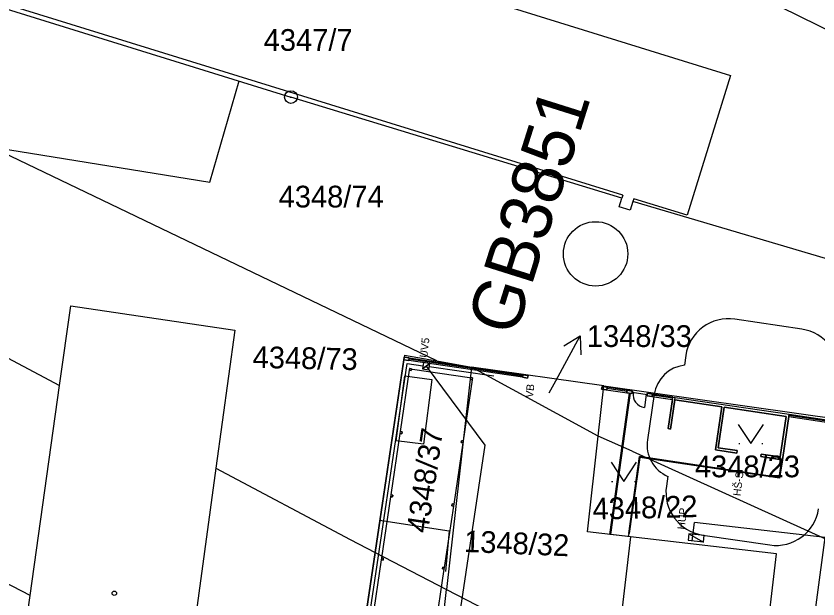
# Model space of a CAD drawing. Extents: x -735036 to -734743, y -1144813 to -1144181.
# Drawn here: x -734898.4 to -734835.7, y -1144525.7 to -1144480 of the extents above; entities that cross this region are included whole.
import ezdxf

# ---------------------------------------------------------------- set-up
doc = ezdxf.new("R2010")
doc.units = 0
for name, color, linetype in [('A3_BOURANÉ OBJEKTY', 7, 'Continuous'), ('A3_Netisk', 7, 'Continuous'), ('A3_ODVODŇOVACÍ ŽLAB', 7, 'Continuous'), ('A3_SIT_OBJEKTY_N01', 7, 'Continuous'), ('A3_SIT_PNB', 7, 'Continuous'), ('CKKOTY', 7, 'Continuous'), ('CKPLYN_POTRUBI_NT_PODZ_N', 7, 'Continuous'), ('CKTEXTY_MALE', 7, 'Continuous'), ('hranice pl. určené SŽDC', 7, 'Continuous'), ('Katastr_HRANICE DRÁHY', 7, 'Continuous'), ('Katastr_Hranice parcel', 7, 'Continuous'), ('Katastr_Parcelní čísla', 7, 'Continuous'), ('Katastr_Značky kultur', 7, 'Continuous'), ('SO05_CKKANALIZACE_JEDNOTNA_PODZ_N', 7, 'Continuous'), ('ŽBP', 7, 'Continuous')]:
    doc.layers.add(name, color=color, linetype=linetype)

msp = doc.modelspace()

# ---------------------------------------------------------------- linework, layer by layer
msp.add_line((-734866.625, -1144507.658), (-734866.057, -1144507.237))
for points in [[(-734866.625, -1144507.658), (-734866.13, -1144507.731), (-734866.057, -1144507.237), (-734866.551, -1144507.163)], [(-734866.625, -1144507.658), (-734866.13, -1144507.731), (-734866.057, -1144507.237)]]:
    msp.add_lwpolyline(points, close=True)
at = {"layer": 'A3_BOURANÉ OBJEKTY'}
msp.add_lwpolyline([(-734866.552, -1144513.548), (-734868.669, -1144513.299), (-734867.996, -1144508.198), (-734865.894, -1144508.483)], close=True, dxfattribs=at)
msp.add_lwpolyline([(-734869.977, -1144519.507), (-734864.523, -1144520.336), (-734864.819, -1144523.525)], dxfattribs=at)
at = {"layer": 'A3_Netisk'}
msp.add_line((-734838.465, -1144514.774), (-734837.936, -1144511.213), dxfattribs=at)
at = {"layer": 'A3_ODVODŇOVACÍ ŽLAB'}
for points in [[(-734870.972, -1144528.414), (-734867.824, -1144507.227), (-734866.588, -1144507.411)], [(-734861.049, -1144508.234), (-734866.093, -1144507.484)]]:
    msp.add_lwpolyline(points, dxfattribs=at)
at = {"layer": 'A3_SIT_OBJEKTY_N01'}
for p, q in [((-734867.491, -1144507.64), (-734867.62, -1144507.621)), ((-734867.487, -1144507.681), (-734867.483, -1144507.651)), ((-734862.694, -1144508.352), (-734862.823, -1144508.333)), ((-734850.626, -1144509.529), (-734850.597, -1144509.332)), ((-734850.597, -1144509.332), (-734850.201, -1144509.39)), ((-734850.201, -1144509.39), (-734850.23, -1144509.588)), ((-734851.963, -1144520.613), (-734850.421, -1144509.56)), ((-734850.371, -1144509.567), (-734851.914, -1144520.619)), ((-734850.23, -1144509.588), (-734850.626, -1144509.529)), ((-734850.421, -1144509.56), (-734850.371, -1144509.567)), ((-734849.043, -1144509.765), (-734849.014, -1144509.567)), ((-734848.648, -1144509.823), (-734849.043, -1144509.765)), ((-734849.014, -1144509.567), (-734848.618, -1144509.626)), ((-734848.618, -1144509.626), (-734848.648, -1144509.823)), ((-734847.403, -1144512.334), (-734847.036, -1144509.861)), ((-734846.867, -1144510.088), (-734847.205, -1144512.363)), ((-734847.036, -1144509.861), (-734837.936, -1144511.213)), ((-734843.207, -1144510.632), (-734846.867, -1144510.088)), ((-734843.707, -1144513.995), (-734843.207, -1144510.632)), ((-734843.01, -1144510.661), (-734843.48, -1144513.826)), ((-734838.163, -1144511.381), (-734843.01, -1144510.661)), ((-734837.936, -1144511.213), (-734838.465, -1144514.774)), ((-734838.633, -1144514.546), (-734838.163, -1144511.381)), ((-734847.205, -1144512.363), (-734847.403, -1144512.334)), ((-734843.48, -1144513.826), (-734841.996, -1144514.047)), ((-734842.026, -1144514.245), (-734843.707, -1144513.995)), ((-734841.996, -1144514.047), (-734842.026, -1144514.245)), ((-734840.146, -1144514.524), (-734840.117, -1144514.326)), ((-734840.117, -1144514.326), (-734838.633, -1144514.546)), ((-734850.488, -1144520.532), (-734849.65, -1144514.527)), ((-734849.607, -1144514.584), (-734850.438, -1144520.538)), ((-734849.65, -1144514.527), (-734838.72, -1144516.151)), ((-734838.678, -1144516.208), (-734849.607, -1144514.584)), ((-734838.465, -1144514.774), (-734840.146, -1144514.524)), ((-734838.72, -1144516.151), (-734838.514, -1144514.766)), ((-734838.465, -1144514.774), (-734838.678, -1144516.208)), ((-734838.514, -1144514.766), (-734838.465, -1144514.774)), ((-734851.914, -1144520.619), (-734851.963, -1144520.613)), ((-734850.438, -1144520.538), (-734850.488, -1144520.532))]:
    msp.add_line(p, q, dxfattribs=at)
for points in [[(-734888.44, -1144569.554), (-734887.65, -1144563.8), (-734885.58, -1144548.75), (-734874.6, -1144550.79), (-734868.084, -1144506.936)], [(-734867.659, -1144506.797), (-734867.689, -1144506.994), (-734868.084, -1144506.936), (-734868.055, -1144506.738), (-734867.659, -1144506.797)], [(-734858.772, -1144508.218), (-734867.674, -1144506.895)], [(-734865.623, -1144528.137), (-734864.911, -1144523.339), (-734865.059, -1144523.317), (-734865.037, -1144523.169), (-734864.889, -1144523.191), (-734864.176, -1144518.394), (-734864.324, -1144518.372), (-734864.302, -1144518.223), (-734864.154, -1144518.245), (-734863.441, -1144513.448), (-734863.589, -1144513.426), (-734863.567, -1144513.278), (-734863.419, -1144513.3), (-734862.706, -1144508.502), (-734862.855, -1144508.48), (-734862.838, -1144508.372), (-734862.937, -1144508.357), (-734867.389, -1144507.696), (-734867.487, -1144507.681), (-734867.504, -1144507.79), (-734867.652, -1144507.767), (-734868.365, -1144512.565), (-734868.216, -1144512.587), (-734868.238, -1144512.735), (-734868.387, -1144512.713), (-734869.099, -1144517.511), (-734868.951, -1144517.533), (-734868.973, -1144517.681), (-734869.122, -1144517.659), (-734869.834, -1144522.456), (-734869.686, -1144522.478), (-734869.708, -1144522.627), (-734869.856, -1144522.605), (-734870.569, -1144527.402)], [(-734867.631, -1144507.629), (-734867.652, -1144507.767), (-734867.504, -1144507.79), (-734867.487, -1144507.681)], [(-734858.391, -1144508.376), (-734858.786, -1144508.317), (-734858.757, -1144508.119), (-734858.361, -1144508.178), (-734858.391, -1144508.376)], [(-734862.834, -1144508.342), (-734862.838, -1144508.372), (-734862.855, -1144508.48), (-734862.706, -1144508.502), (-734862.686, -1144508.364)], [(-734852.209, -1144509.294), (-734852.604, -1144509.236), (-734852.575, -1144509.038), (-734852.179, -1144509.097), (-734852.209, -1144509.294)], [(-734850.611, -1144509.431), (-734852.194, -1144509.195)], [(-734850.136, -1144509.501), (-734850.216, -1144509.489)], [(-734849.029, -1144509.666), (-734849.108, -1144509.654), (-734849.261, -1144510.683)], [(-734847.05, -1144509.96), (-734848.633, -1144509.724)], [(-734833.45, -1144511.98), (-734837.95, -1144511.312)], [(-734868.216, -1144512.587), (-734868.365, -1144512.565), (-734868.387, -1144512.713), (-734868.238, -1144512.735), (-734868.216, -1144512.587)], [(-734863.419, -1144513.3), (-734863.567, -1144513.278), (-734863.589, -1144513.426), (-734863.441, -1144513.448), (-734863.419, -1144513.3)], [(-734868.951, -1144517.533), (-734869.099, -1144517.511), (-734869.122, -1144517.659), (-734868.973, -1144517.681), (-734868.951, -1144517.533)], [(-734864.154, -1144518.245), (-734864.302, -1144518.223), (-734864.324, -1144518.372), (-734864.176, -1144518.394), (-734864.154, -1144518.245)], [(-734869.686, -1144522.478), (-734869.834, -1144522.456), (-734869.856, -1144522.605), (-734869.708, -1144522.627), (-734869.686, -1144522.478)], [(-734864.889, -1144523.191), (-734865.037, -1144523.169), (-734865.059, -1144523.317), (-734864.911, -1144523.339), (-734864.889, -1144523.191)]]:
    msp.add_lwpolyline(points, dxfattribs=at)
for points in [[(-734868.055, -1144506.738), (-734868.084, -1144506.936), (-734867.689, -1144506.994), (-734867.659, -1144506.797)], [(-734867.659, -1144506.797), (-734858.757, -1144508.119), (-734858.786, -1144508.317), (-734867.689, -1144506.994)], [(-734858.786, -1144508.317), (-734858.391, -1144508.376), (-734858.361, -1144508.178), (-734858.757, -1144508.119)], [(-734852.604, -1144509.236), (-734852.209, -1144509.294), (-734852.179, -1144509.097), (-734852.575, -1144509.038)], [(-734852.604, -1144509.236), (-734850.23, -1144509.588), (-734850.201, -1144509.39), (-734852.575, -1144509.038)], [(-734850.626, -1144509.529), (-734850.23, -1144509.588), (-734850.201, -1144509.39), (-734850.201, -1144509.39), (-734850.597, -1144509.332)], [(-734851.914, -1144520.619), (-734851.963, -1144520.613), (-734850.421, -1144509.56), (-734850.371, -1144509.567)], [(-734850.488, -1144520.532), (-734850.517, -1144520.781), (-734851.914, -1144520.619), (-734850.371, -1144509.567), (-734850.23, -1144509.588), (-734850.216, -1144509.489), (-734849.029, -1144509.666), (-734849.043, -1144509.765), (-734847.065, -1144510.059), (-734847.403, -1144512.334), (-734847.205, -1144512.363), (-734846.867, -1144510.088), (-734843.207, -1144510.632), (-734843.707, -1144513.995), (-734842.026, -1144514.245), (-734841.996, -1144514.047), (-734843.48, -1144513.826), (-734843.01, -1144510.661), (-734838.163, -1144511.381), (-734838.633, -1144514.546), (-734840.117, -1144514.326), (-734840.146, -1144514.524), (-734838.514, -1144514.766), (-734838.72, -1144516.151), (-734838.72, -1144516.151), (-734849.65, -1144514.527)], [(-734849.014, -1144509.567), (-734849.043, -1144509.765), (-734848.648, -1144509.823), (-734848.618, -1144509.626)], [(-734847.036, -1144509.861), (-734848.618, -1144509.626), (-734848.648, -1144509.823), (-734847.065, -1144510.059)], [(-734842.026, -1144514.245), (-734843.707, -1144513.995), (-734843.207, -1144510.632), (-734846.867, -1144510.088), (-734847.205, -1144512.363), (-734847.403, -1144512.334), (-734847.036, -1144509.861), (-734837.936, -1144511.213), (-734838.465, -1144514.774), (-734840.146, -1144514.524), (-734840.117, -1144514.326), (-734838.633, -1144514.546), (-734838.163, -1144511.381), (-734843.01, -1144510.661), (-734843.48, -1144513.826), (-734841.996, -1144514.047)], [(-734833.464, -1144512.079), (-734837.965, -1144511.411), (-734837.936, -1144511.213), (-734833.435, -1144511.881)], [(-734838.465, -1144514.774), (-734838.678, -1144516.208), (-734849.607, -1144514.584), (-734850.438, -1144520.538), (-734850.488, -1144520.532), (-734849.65, -1144514.527), (-734838.72, -1144516.151), (-734838.514, -1144514.766)]]:
    msp.add_lwpolyline(points, close=True, dxfattribs=at)
for centre, radius, start, end in [((-734867.621, -1144507.63), 0.01, 81.54908, 171.54908), ((-734867.493, -1144507.65), 0.01, 351.54908, 81.54908), ((-734862.824, -1144508.343), 0.01, 81.54908, 171.54908), ((-734862.695, -1144508.362), 0.01, 351.54908, 81.54908), ((-734849.108, -1144509.654), 1.04, 171.54994, 261.54908)]:
    msp.add_arc(centre, radius, start, end, dxfattribs=at)
at = {"layer": 'A3_SIT_PNB'}
for points in [[(-734836.945, -1144504.546), (-734842.187, -1144503.767)], [(-734846.016, -1144506.605), (-734846.13, -1144507.371)], [(-734848.49, -1144509.645), (-734849.019, -1144513.206)], [(-734847.422, -1144516.067), (-734847.536, -1144516.833)], [(-734844.698, -1144520.662), (-734839.455, -1144521.44)]]:
    msp.add_lwpolyline(points, dxfattribs=at)
for centre, radius, start, end in [((-734842.683, -1144507.1), 3.37, 81.54908, 171.54908), ((-734837.44, -1144507.879), 3.37, 351.54908, 81.54908), ((-734845.834, -1144510.039), 2.685, 96.32984, 171.54908), ((-734846.363, -1144513.6), 2.685, 171.54908, 246.76833), ((-734844.202, -1144517.328), 3.37, 171.54908, 261.54908), ((-734838.96, -1144518.107), 3.37, 261.54908, 351.54908)]:
    msp.add_arc(centre, radius, start, end, dxfattribs=at)
at = {"layer": 'CKKOTY'}
msp.add_line((-734847.205, -1144512.363), (-734846.838, -1144509.89), dxfattribs=at)
at = {"layer": 'CKPLYN_POTRUBI_NT_PODZ_N'}
msp.add_line((-734845.514, -1144521.105), (-734845.346, -1144519.67), dxfattribs=at)
msp.add_lwpolyline([(-734840.638, -1144562.238), (-734835.108, -1144520.855), (-734845.346, -1144519.67)], dxfattribs=at)
for points in [[(-734844.641, -1144521.205), (-734844.583, -1144520.71), (-734845.775, -1144520.57), (-734845.833, -1144521.066)], [(-734844.633, -1144521.222), (-734844.583, -1144520.71), (-734845.773, -1144520.571)]]:
    msp.add_lwpolyline(points, close=True, dxfattribs=at)
at = {"layer": 'hranice pl. určené SŽDC'}
for p, q in [((-734883.27, -1144493.05), (-734880.96, -1144485.12)), ((-734900.35, -1144490.28), (-734883.27, -1144493.05))]:
    msp.add_line(p, q, dxfattribs=at)
at = {"layer": 'Katastr_HRANICE DRÁHY'}
msp.add_line((-734861.21, -1144468.1), (-734830.02, -1144483.57), dxfattribs=at)
for points in [[(-734895.01, -1144508.96), (-734894.14, -1144502.71)], [(-734894.14, -1144502.71), (-734881.31, -1144504.63)], [(-734881.31, -1144504.63), (-734882.78, -1144515.44)], [(-734897.31, -1144525.39), (-734895.01, -1144508.96)], [(-734882.78, -1144515.44), (-734885, -1144531.74)], [(-734898.48, -1144533.77), (-734897.31, -1144525.39)]]:
    msp.add_lwpolyline(points, dxfattribs=at)
at = {"layer": 'Katastr_Hranice parcel'}
for points in [[(-734902.72, -1144466.02), (-734842.51, -1144484.69)], [(-734917.71, -1144473.71), (-734876.91, -1144486.38)], [(-734850.95, -1144494.07), (-734906.11, -1144476.96)], [(-734942.87, -1144483.49), (-734895.01, -1144508.96)], [(-734865.5, -1144507.03), (-734912.56, -1144484.42)], [(-734842.51, -1144484.69), (-734845.92, -1144495.63)], [(-734851.02, -1144494.29), (-734876.91, -1144486.38)], [(-734851.22, -1144494.96), (-734851.02, -1144494.29)], [(-734850.95, -1144494.07), (-734851.02, -1144494.29)], [(-734850.09, -1144494.34), (-734850.16, -1144494.56)], [(-734845.92, -1144495.63), (-734850.09, -1144494.34)], [(-734850.37, -1144495.22), (-734851.22, -1144494.96)], [(-734850.16, -1144494.56), (-734850.37, -1144495.22)], [(-734831.84, -1144499.97), (-734850.16, -1144494.56)], [(-734868.03, -1144506.57), (-734870.33, -1144522.02)], [(-734868.03, -1144506.57), (-734865.5, -1144507.03)], [(-734865.5, -1144507.03), (-734862.79, -1144507.52)], [(-734862.79, -1144507.52), (-734864.73, -1144524.92)], [(-734852.42, -1144508.98), (-734862.79, -1144507.52)], [(-734852.87, -1144512.92), (-734862.79, -1144507.52)], [(-734852.87, -1144512.92), (-734852.42, -1144508.98)], [(-734852.42, -1144508.98), (-734833.68, -1144511.64)], [(-734853.72, -1144520.41), (-734852.87, -1144512.92)], [(-734850.22, -1144514.11), (-734852.87, -1144512.92)], [(-734850.22, -1144514.11), (-734834.23, -1144521.36)], [(-734882.78, -1144515.44), (-734872.29, -1144521)], [(-734850.35, -1144520.8), (-734853.72, -1144520.41)], [(-734872.29, -1144521), (-734870.33, -1144522.02)], [(-734850.35, -1144520.8), (-734851.62, -1144531.72)], [(-734838.91, -1144522.14), (-734850.35, -1144520.8)], [(-734897.31, -1144525.39), (-734905.03, -1144521.41)], [(-734870.33, -1144522.02), (-734872.73, -1144538.19)], [(-734870.33, -1144522.02), (-734864.73, -1144524.92)], [(-734840.76, -1144537.68), (-734838.91, -1144522.14)], [(-734866.58, -1144541.54), (-734864.73, -1144524.92)], [(-734864.73, -1144524.92), (-734851.62, -1144531.72)]]:
    msp.add_lwpolyline(points, dxfattribs=at)
at = {"layer": 'Katastr_Parcelní čísla'}
for p, q in [((-734855.563, -1144505.849), (-734854.284, -1144505.063)), ((-734856.7, -1144509.52), (-734856.19, -1144508.58))]:
    msp.add_line(p, q, dxfattribs=at)
msp.add_lwpolyline([(-734856.19, -1144508.58), (-734854.284, -1144505.063), (-734854.244, -1144506.563)], dxfattribs=at)
at = {"layer": 'Katastr_Značky kultur'}
for p, q in [((-734876.96, -1144486.38), (-734876.86, -1144486.38)), ((-734841.88, -1144513.5), (-734841.78, -1144513.5)), ((-734840.08, -1144513.5), (-734839.98, -1144513.5)), ((-734851.82, -1144516.47), (-734851.72, -1144516.47)), ((-734850.02, -1144516.47), (-734849.92, -1144516.47))]:
    msp.add_line(p, q, dxfattribs=at)
for points in [[(-734841.93, -1144512), (-734840.93, -1144513.5), (-734839.93, -1144512)], [(-734851.87, -1144514.97), (-734850.87, -1144516.47), (-734849.87, -1144514.97)]]:
    msp.add_lwpolyline(points, dxfattribs=at)
for centre, radius in [((-734876.91, -1144486.38), 0.499), ((-734890.73, -1144525.22), 0.175)]:
    msp.add_circle(centre, radius, dxfattribs=at)
at = {"layer": 'SO05_CKKANALIZACE_JEDNOTNA_PODZ_N'}
msp.add_lwpolyline([(-734866.341, -1144507.447), (-734861.751, -1144513.639), (-734864.21, -1144530.193), (-734864.357, -1144531.183), (-734866.393, -1144544.885), (-734866.467, -1144545.379), (-734868.027, -1144555.885), (-734873.869, -1144554.902)], dxfattribs=at)
at = {"layer": 'ŽBP'}
msp.add_circle((-734853.076, -1144498.652), 2.52, dxfattribs=at)

# ---------------------------------------------------------------- texts
at = {"layer": 'CKTEXTY_MALE'}
for s, p in [('UV5', (-734866.251, -1144506.804)), ('VB', (-734857.985, -1144509.937)), ('HŠ-S', (-734841.727, -1144517.637)), ('HUP', (-734846.102, -1144520.255))]:
    msp.add_text(s, height=0.6, rotation=83.326, dxfattribs=at).set_placement(p)
at = {"layer": 'Katastr_Parcelní čísla'}
for s, p in [('4347/7', (-734879.043, -1144482.76)), ('4348/74', (-734877.873, -1144495.02)), ('1348/33', (-734853.76, -1144505.94)), ('4348/23', (-734845.307, -1144516.14))]:
    msp.add_text(s, height=1.7, dxfattribs=at).set_placement(p)
for s, rotation, p in [('4348/73', 358.76214, (-734879.926, -1144507.576)), ('4348/37', 81.65502, (-734866.195, -1144520.566)), ('4348/22', 1.45107, (-734853.296, -1144519.463)), ('1348/32', 357.57765, (-734863.39, -1144521.981))]:
    msp.add_text(s, height=1.7, rotation=rotation, dxfattribs=at).set_placement(p)
at = {"layer": 'ŽBP'}
msp.add_text('GB3851', height=3.9996, rotation=72.49543, dxfattribs=at).set_placement((-734859.36, -1144505.219))

doc.saveas('drawing.dxf')
